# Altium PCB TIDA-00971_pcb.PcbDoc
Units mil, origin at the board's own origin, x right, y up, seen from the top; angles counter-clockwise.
Board outline 1950 x 2000 mil, 2 copper layers (Top Layer, Bottom Layer), stack 62 mil thick; 42 components, 22 nets, 111 pads, 73 vias.
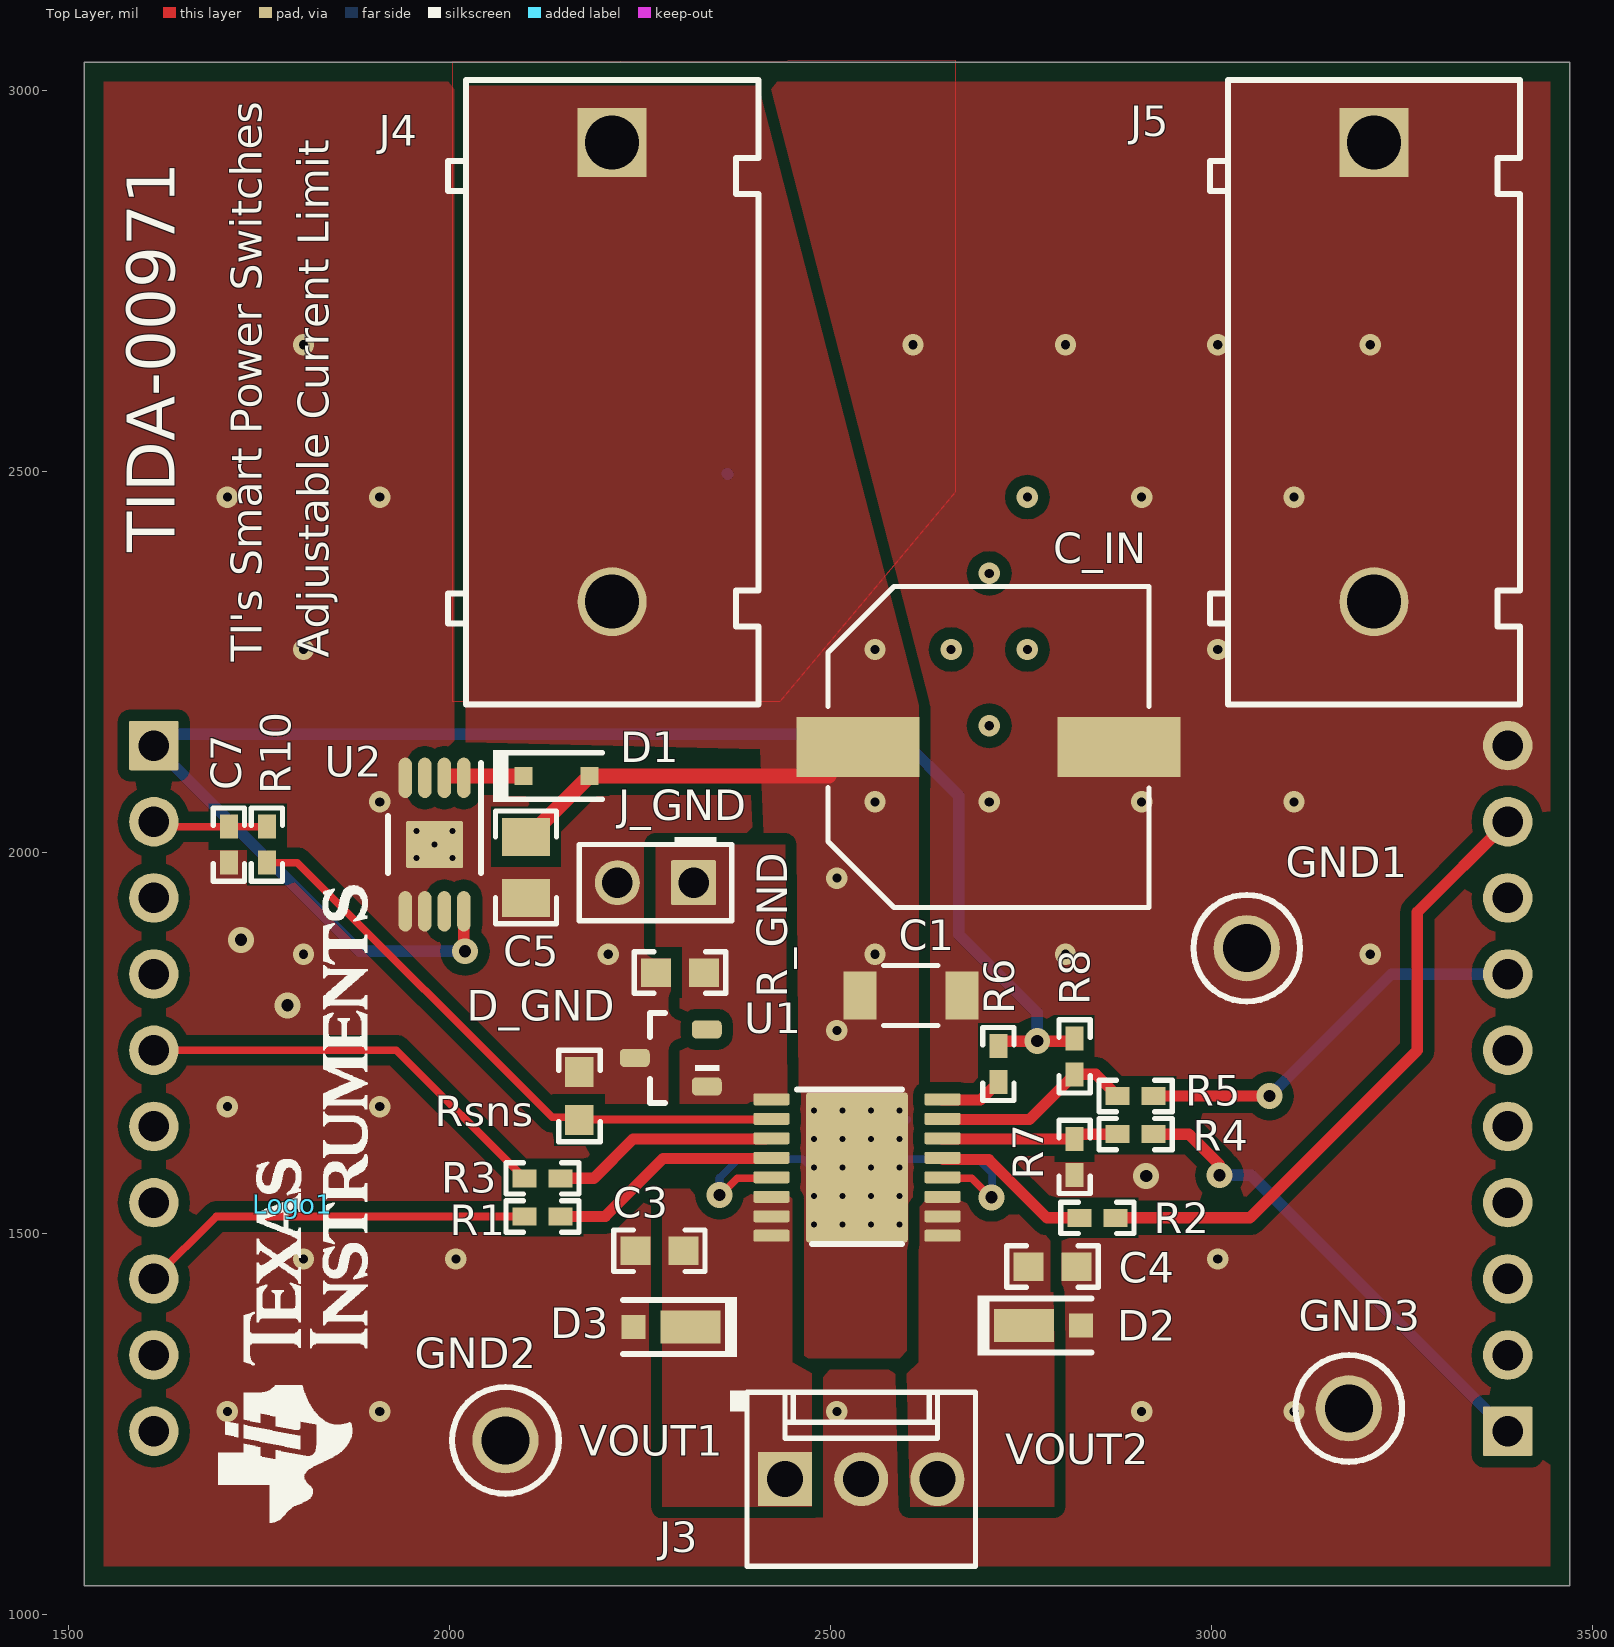
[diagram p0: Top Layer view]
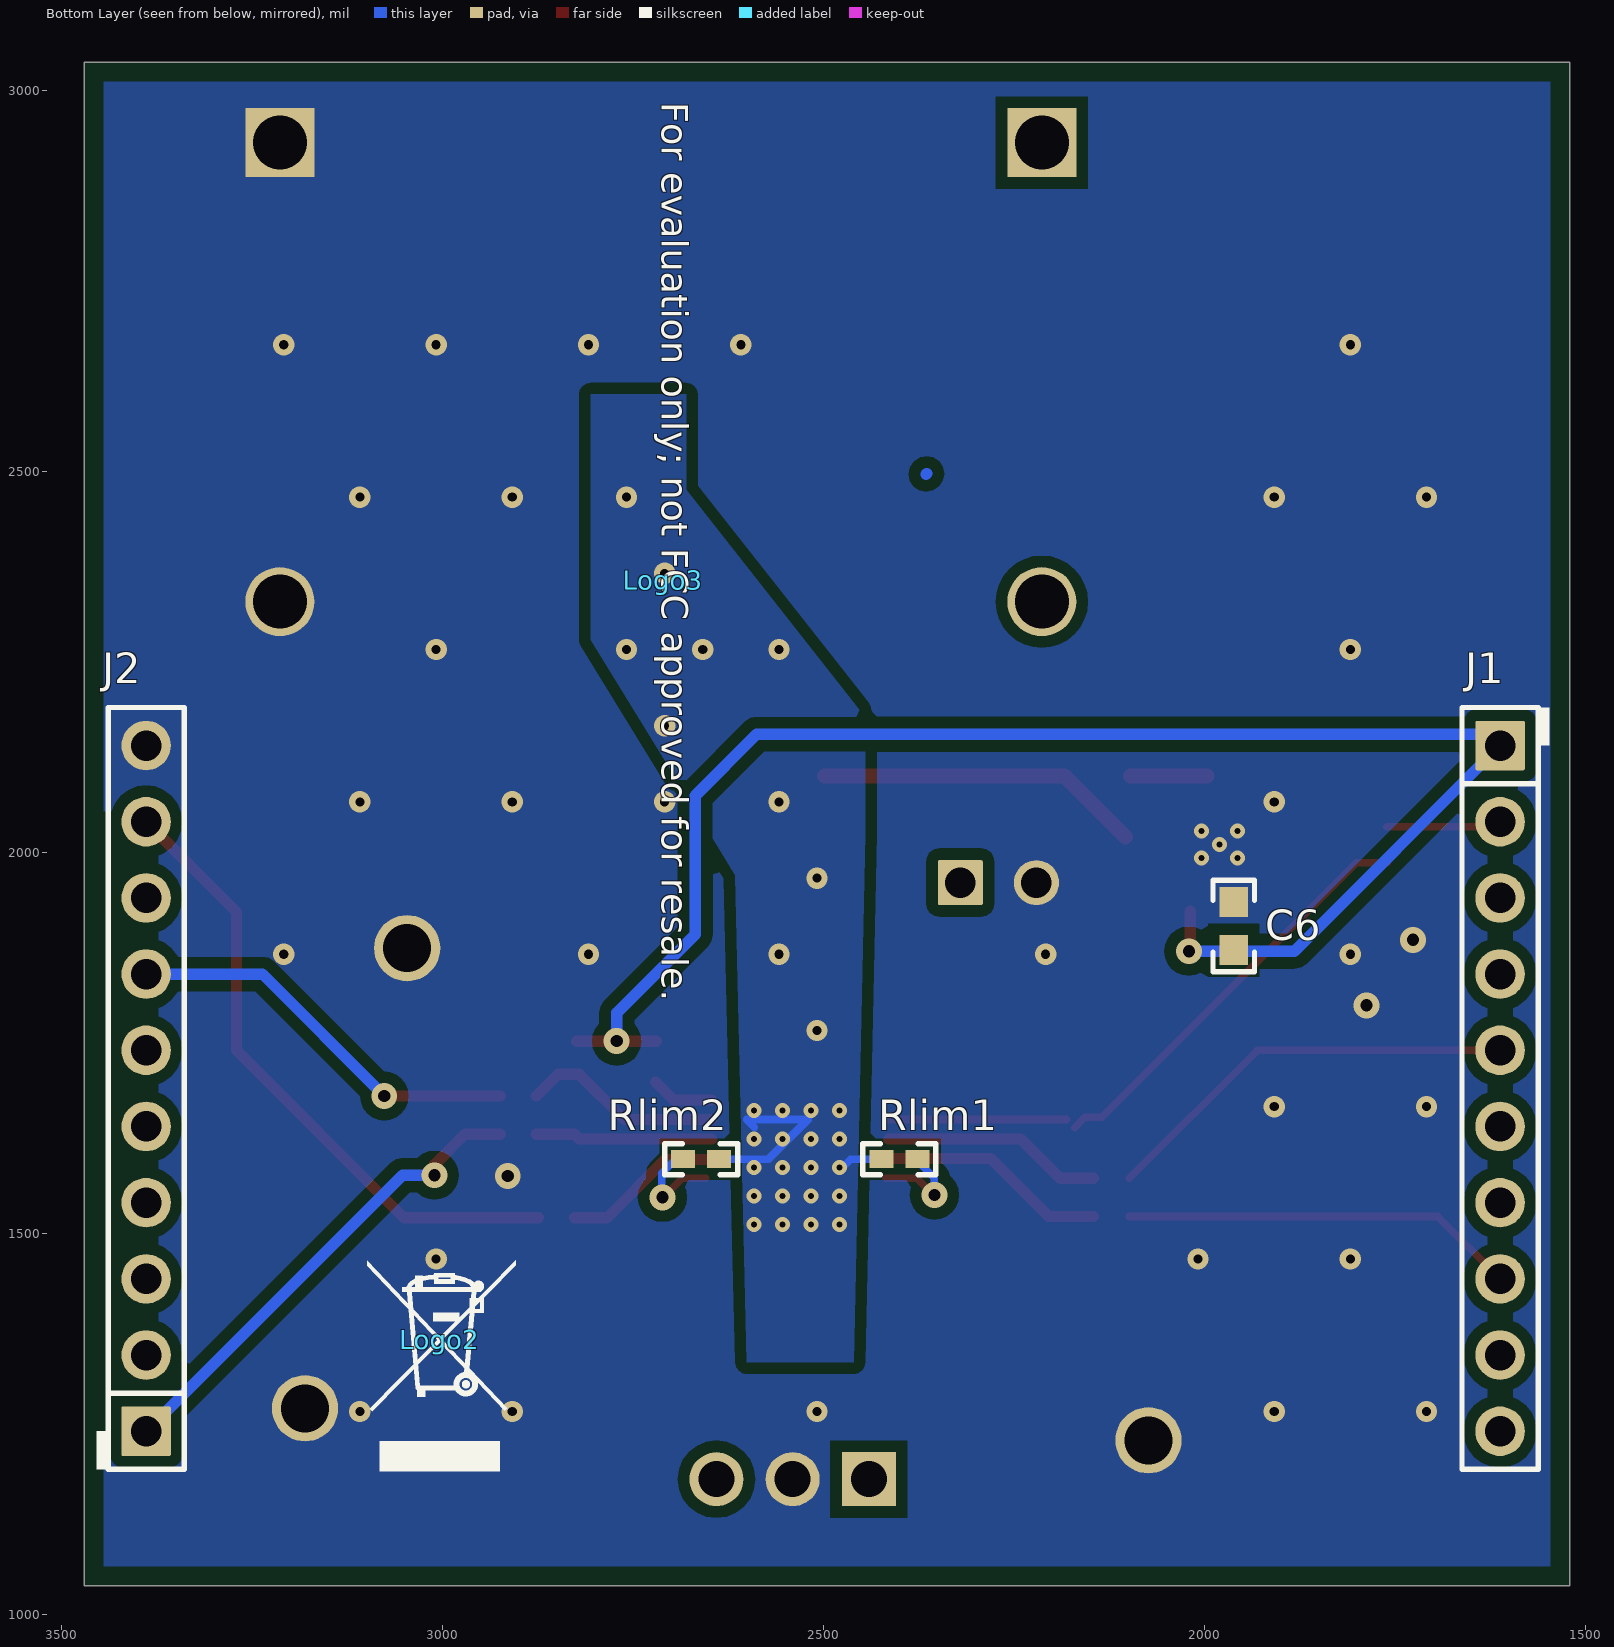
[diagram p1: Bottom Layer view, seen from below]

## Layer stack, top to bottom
Top Solder: solder mask 0.4, Solder Resist, Dk 3.5
Top Layer: signal copper 1.4
Dielectric1: core 59.2, FR-4, Dk 4.8
Bottom Layer: signal copper 1.4
Bottom Solder: solder mask 0.4, Solder Resist, Dk 3.5

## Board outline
1520,1037 3470,1037 3470,3037 1520,3037

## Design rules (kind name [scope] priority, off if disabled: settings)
AcuteAngle [All] p1: minimum=4.50000000000000E+0001 checktracksonly=FALSE
AssemblyTestPointUsage [All] p1: valid=2
BoardOutlineClearance BoardOutlineClearance_banana [(HasFootprint('571-0100') AND HasFootprint('571-0500'))] p1: gap=0 ignorepadtopadclearanceinfootprint=FALSE
BoardOutlineClearance BoardOutlineClearance_MountingHoles [OnCopper and InComponentClass('Mounting Holes')] p2: gap=40 ignorepadtopadclearanceinfootprint=FALSE
BoardOutlineClearance BoardOutlineClearance_Poly [OnCopper and IsPoly] p3: gap=25 ignorepadtopadclearanceinfootprint=FALSE
BoardOutlineClearance [OnCopper and Not InComponentClass('Logo') and not InComponentClass('FiducialMark') and not InRegion(1000,500,4000,800) and not InPoly] p4: gap=75 ignorepadtopadclearanceinfootprint=FALSE except(10: THPad-OutlineEdge THPad-CavityEdge THPad-CutoutEdge THPad-SplitBarrior THPad-SplitContinuation; 20: Track-OutlineEdge Track-CavityEdge Track-CutoutEdge Track-SplitBarrior Track-SplitContinuation)
Clearance Clearance_Keepouts [((IsTrack Or IsArc) And Not InPoly) And IsFree and IsKeepOut vs ((IsTrack Or IsArc) And Not InPoly) And IsFree and IsKeepOut] p1: gap=0 ignorepadtopadclearanceinfootprint=FALSE
Clearance Clearance_Poly [InPolygon] p2: gap=15 ignorepadtopadclearanceinfootprint=FALSE
Clearance Clearance_FiducialMark [IsKeepOut and InComponentClass('FiducialMark') vs IsPad and InComponentClass('FiducialMark')] p3: gap=0 ignorepadtopadclearanceinfootprint=FALSE
Clearance [All] p4: gap=7.87 ignorepadtopadclearanceinfootprint=FALSE except(0: Arc-Hole Track-Hole SMDPad-Hole THPad-Hole Via-Hole Fill-Hole Poly-Hole Region-Hole Text-Hole)
ComponentClearance ComponentClearance_Logo [(HasFootprint('FCC_disclaimer') AND HasFootprint('TI_Stacked_Overlay_Small') AND HasFootprint('WEEE_Minimum') AND HasFootprint('WorksWithTILaunchPad'))] p1: gap=0 collisioncheckmode=3 verticalgap=0 showdistances=FALSE
ComponentClearance ComponentClearance_MountingHoles_FiducialMarks [InComponentClass('Mounting Holes') vs InComponentClass('FiducialMark')] p2: gap=50 collisioncheckmode=3 verticalgap=10 showdistances=FALSE
ComponentClearance ComponentClearance_Shunt [InComponentClass('Header') vs InComponentClass('Shunt')] p3: gap=0 collisioncheckmode=3 verticalgap=0 showdistances=FALSE
ComponentClearance ComponentClearance_ScrewToNut [(HasFootprint('NY PMS 440 0025 PH')) vs (HasFootprint('Keystone_1902C'))] p4: gap=5 collisioncheckmode=3 verticalgap=10 showdistances=FALSE
ComponentClearance ComponentClearance_MountingHoles [InComponentClass('Mounting Holes')] p5: gap=250 collisioncheckmode=3 verticalgap=100000 showdistances=FALSE
ComponentClearance ComponentClearance_SmallPassives [HasFootprint('0201*') or HasFootprint('0402*') or HasFootprint('0508') or HasFootprint('0603*') or HasFootprint('0612') or HasFootprint('0805*') or HasFootprint('0815*') or HasFootprint('0830*') or HasFootprint('1206*') or HasFootprint('1210*') or HasFootprint('1808*') or HasFootprint('1812*') or HasFootprint('1825*') or HasFootprint('2010*') or HasFootprint('2220*') or HasFootprint('2225*') or HasFootprint('2512*') or HasFootprint('2728*') or HasFootprint('3518*') vs HasFootprint('0201*') or HasFootprint('0402*') or HasFootprint('0508') or HasFootprint('0603*') or HasFootprint('0612') or HasFootprint('0805*') or HasFootprint('0815*') or HasFootprint('0830*') or HasFootprint('1206*') or HasFootprint('1210*') or HasFootprint('1808*') or HasFootprint('1812*') or HasFootprint('1825*') or HasFootprint('2010*') or HasFootprint('2220*') or HasFootprint('2225*') or HasFootprint('2512*') or HasFootprint('2728*') or HasFootprint('3518*')] p6: gap=14.96 collisioncheckmode=3 verticalgap=10 showdistances=FALSE
ComponentClearance ComponentClearance_THtoSMT [IsThruComponent vs IsSMTComponent] p7: gap=40 collisioncheckmode=3 verticalgap=30 showdistances=FALSE
ComponentClearance ComponentClearance_THtoTH [IsThruComponent vs IsThruComponent] p8: gap=30 collisioncheckmode=3 verticalgap=30 showdistances=FALSE
ComponentClearance [All] p9: gap=30 collisioncheckmode=3 verticalgap=10 showdistances=FALSE
DiffPairsRouting [All] p1: maxlimit=100 minlimit=10 mostfreqgap=10 toplayer_minwidth=15 toplayer_maxwidth=15 toplayer_prefwidth=15 bottomlayer_minwidth=15 bottomlayer_maxwidth=15 bottomlayer_prefwidth=15 maxuncoupledlength=1000
FabricationTestPointUsage TestPointUsage [All] p1: valid=2 allowmultiple=FALSE
FabricationTestpoint Testpoint [All] p1: side=3 testpointundercomponent=TRUE minsize=40 maxsize=100 preferedsize=60 minholesize=0 maxholesize=40 preferedholesize=32 testpointgrid=1 allowsidetop=TRUE allowsidebottom=TRUE usegrid=TRUE gridtolerance=0.01
FanoutControl Fanout_LCC [IsLCC] p1: bgadir=Out bgaviamode=Centered fanoutstyle=Auto fanoutdirection=Alternating viagrid=1 // Fanout_LCC (Default Rule)
FanoutControl Fanout_BGA [IsBGA] p2: bgadir=Out bgaviamode=Centered fanoutstyle=Auto fanoutdirection=Alternating viagrid=1 // Fanout_BGA (Default Rule)
FanoutControl Fanout_Default [All] p4: bgadir=Out bgaviamode=Centered fanoutstyle=Auto fanoutdirection=Alternating viagrid=1 // Fanout_Default (Default Rule)
FanoutControl Fanout_Small [(CompPinCount < 5)] p5: bgadir=Out bgaviamode=Centered fanoutstyle=Auto fanoutdirection=OutThenIn viagrid=1 // Fanout_Small (Default Rule)
HoleSize [All] p1: absolutevalues=TRUE maxlimit=251 minlimit=7.87 maxpercent=80.000 minpercent=20.000
MinimumAnnularRing MinimumAnnularRing_ThermalPadVias [IsVia and InAnyComponent] p1: minimumring=5.91
MinimumAnnularRing [All] p2: minimumring=8
MinimumSolderMaskSliver MinimumSolderMaskSliver_Logo [InComponentClass('Logo') vs InComponentClass('Logo')] p1: minsoldermaskwidth=0.7
MinimumSolderMaskSliver [All] p2: minsoldermaskwidth=3.94
PlaneClearance [All] p1: clearance=15
PlaneConnect [All] p1: planeconnectstyle=Relief reliefexpansion=10 reliefentries=4 reliefconductorwidth=10 reliefairgap=10
PolygonConnect [All] p1: connectstyle=Direct reliefconductorwidth=10 reliefentries=4 polygonreliefangle="90 Angle" airgapwidth=10
RoutingVias ThermalPadVias [IsVia and InAnyComponent] p1: holewidth=7.87 width=19.68 viastyle="Through Hole" minholewidth=7.87 minwidth=19.68 maxholewidth=12.99 maxwidth=23.62
RoutingVias [All] p2: holewidth=16 width=34 viastyle="Through Hole" minholewidth=7.87 minwidth=26 maxholewidth=40 maxwidth=65
SilkToBoardRegionClearance [Not ((IsComment or IsDesignator) And (Hide <> 'False')) and not InRegion(1000,500,4000,800)] p1:
SilkToSilkClearance SilkToSilkClearance_Pb-FreeLogo [(HasFootprint('Pb-Free_Overlay_Medium') OR HasFootprint('Pb-Free_Overlay_Small')) vs (HasFootprint('Pb-Free_Overlay_Medium') OR HasFootprint('Pb-Free_Overlay_Small'))] p1: silktosilkclearance=0
SilkToSilkClearance [All] p2: silktosilkclearance=4
SilkToSolderMaskClearance SilkToComponentPadClearance [(IsPad or IsFill or IsRegion) and InAnycomponent] p1: minsilkscreentomaskgap=5 clearancetoexposedcopper=TRUE
SilkToSolderMaskClearance "Silk to Solder Mask Opening" [All] p2: minsilkscreentomaskgap=4 clearancetoexposedcopper=FALSE
SolderMaskExpansion [All] p1: expansion=1.97
Width [All] p1: maxlimit=100 minlimit=6 preferedwidth=10 checkconnectedcopper=TRUE
14 further rules are at their usual default settings.

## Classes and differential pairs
component class AssemblyNote: ZZ1 ZZ2 ZZ3 ZZ4
component class EVM_Hardware: Logo1 Logo2 Logo3 ZZ1 ZZ2 ZZ3 ZZ4
component class Logo: Logo1
component class TIDA-00971_main_schematic: C1 C3 C4 C5 C6 C7 C_IN D1 D2 D3 D_GND GND1 GND2 GND3 J1 J2 J3 J4 J5 J_GND R1 R2 R3 R4 R5 R6 R7 R8 R10 R_GND Rlim1 Rlim2 Rsns U1 U2
component class Header: J1 J2 J_GND

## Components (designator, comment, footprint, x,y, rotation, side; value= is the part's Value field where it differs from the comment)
C1 "C1206C225K5RACAUTO7210" 1206_180 2605,1812 r0 top value=2.2uF
C3 "C0603C223K3RACTU" 0603 2275,1477 r180 top value=0.022uF
C4 "C0603C223K3RACTU" 0603 2791,1456 r0 top value=0.022uF
C5 "08055C105K4Z2A" 0805_HV 2100,1980 r270 top value=1uF
C6 "GRT188C81C106ME13D" 0603 1961,1903 r90 bottom value=10uF
C7 "CGA2B2C0G1H101J050BA" 0402 1710,2010 r270 top value=100pF
C_IN "EEE-FK1H151P" SM_RADIAL_G 2707,2138 r0 top value=150uF
D1 "ZLLS400QTA" SOD-323 2140,2100 r0 top value=40V
D2 "MSE1PGHM3/89A" MicroSMP 2779,1379 r0 top value=400V
D3 "MSE1PGHM3/89A" MicroSMP 2290,1377 r180 top value=400V
D_GND "BAS21HMFHT116" SOT-23 2290,1730 r180 top value=200V
GND1 "5011" Keystone5011 3046,1874 r0 top
GND2 "5011" Keystone5011 2073,1228 r0 top
GND3 "5011" Keystone5011 3180,1270 r0 top
J1 "TSW-110-07-G-S" TSW-110-07-G-S 1611.5,1690 r270 bottom
J2 "TSW-110-07-G-S" TSW-110-07-G-S 3388.5,1690 r90 bottom locked
J3 "22-27-2031" MOLEX_22-27-2031 2540,1177 r0 top
J4 "571-0500" 571-0500 2213,2630 r270 top
J5 "571-0100" 571-0100 3213,2630 r270 top
J_GND "PEC02SAAN" CONN_PEC02SAAN 2270,1960 r180 top
Logo1 "Texas Instruments" TI_Stacked_Overlay_Small 1794,1538 r90 top
Logo2 "WEEE logo" WEEE_Minimum 3003,1360 r180 bottom
Logo3 "FCC disclaimer" FCC_disclaimer 2710,2357 r270 bottom
R1 "CRCW040215K0JNED" 0402 2121.65,1521.81 r0 top value=15k
R2 "CRCW040215K0JNED" 0402 2850,1520 r180 top value=15k
R3 "CRCW040215K0JNED" 0402 2121.65,1571.81 r0 top value=15k
R4 "CRCW040215K0JNED" 0402 2900,1630 r0 top value=15k
R5 "CRCW040215K0JNED" 0402 2900,1680 r0 top value=15k
R6 "CRCW040215K0JNED" 0402 2720,1722 r270 top value=15k
R7 "ERJ-2GE0R00X" 0402 2820,1600 r90 top value=0
R8 "ERJ-2GE0R00X" 0402 2820,1732 r270 top value=0
R10 "CRCW040210K0JNED" 0402 1760,2010 r270 top value=10k
R_GND "RC0603JR-074K7L" 0603 2301.98,1841.98 r0 top value=4.7k
Rlim1 "CRCW040220K0FKED" 0402 2400,1597 r180 bottom value=20.0k
Rlim2 "CRCW040224K9FKED" 0402 2660,1597 r0 bottom value=24.9k
Rsns "CRCW06033K01FKEA" 0603 2170,1680 r270 top value=3.01k
U1 "TPS2HB16BQPWPRQ1" TPS1HA08-Q1_L 2534.4,1586.15 r0 top
U2 "TPS7B8233QDGNRQ1" DGN0008D_N 1980,2010 r270 top
ZZ1 "This Assembly Note is for PCB labels only" AssemblyNoteLabel 185,3938 r0 top
ZZ2 "These assemblies are ESD sensitive, ESD precautions shall be observed." AssemblyNote 185,3829.11 r0 top
ZZ3 "These assemblies must be clean and free from flux and all contaminants. Use of no clean flux is not acceptable." AssemblyNote 185,3740.56 r0 top
ZZ4 "These assemblies must comply with workmanship standards IPC-A-610 Class 2, unless otherwise specified." AssemblyNote 185,3652 r0 top

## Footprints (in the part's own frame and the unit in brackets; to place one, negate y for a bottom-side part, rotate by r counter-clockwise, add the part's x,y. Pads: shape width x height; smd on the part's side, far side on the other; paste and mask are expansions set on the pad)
0402 [mm] "0402 from SM-752 data"
  rect 0.8x0.6 smd: 1(-0.6,0) 2(0.6,0)
  silkscreen extent -1.22,-0.52 1.22,0.52, body extent -0.55,-0.3 0.55,0.3, height 0.6
571-0100 [mm] "Deltron Emcon recommended land pattern 2003-10-13"
  rect 2.3x2.3 hole 1.8: 1(-7.65,0)
  round 2.3 hole 1.8: 2(7.65,0)
  silkscreen extent -9.74,-5.47 11.09,4.88, body extent -12.28,-5.48 11.09,4.88, height 12.41
571-0500 [mm] "Deltron Emcon recommended land pattern 2003-10-13"
  rect 2.3x2.3 hole 1.8: 1(-7.65,0)
  round 2.3 hole 1.8: 2(7.65,0)
  silkscreen extent -9.74,-5.47 11.09,4.88, body extent -12.28,-5.48 11.09,4.88, height 12.41
0603 [mm] "0603 from SM-752 data"
  rect 1x0.95 smd: 1(-0.8,0) 2(0.8,0)
  silkscreen extent -1.52,-0.69 1.52,0.69, body extent -0.87,-0.47 0.87,0.47, height 1
0805_HV [mil] "0805 with 30mil clearance between pads"
  rect 50x63 smd: 1(-40,0) 2(40,0)
  silkscreen extent -74,-40 74,40, body extent -43,-29 43,29, height 57
1206_180 [mm] "1206_180"
  rect 1.1x1.6 smd: 1(-1.7,0) 2(1.7,0)
  silkscreen extent -0.9,-1 0.9,1, body extent -1.75,-0.95 1.75,0.95, height 1.8
AssemblyNote [mil] "Assembly Note"
AssemblyNoteLabel [mil] "Assembly Note for PCB Labels"
CONN_PEC02SAAN [mm] "SULLINS"
  rrect7% 1.5x1.5 hole 1.016: 1(-1.27,0)
  round 1.5 hole 1.016: 2(1.27,0)
  silkscreen extent -2.54,-1.52 2.54,1.27, body extent -2.54,-1.27 2.54,1.27, height 8.38
DGN0008D_N [mm] "TSOP, 8-Leads, Body 3x3mm, Pitch 0.65mm, Thermal Pad 1.89x1.57mm, IPC Medium Density"
  rrect100% 1.35x0.45 smd: 1(-2.225,0.975) 2(-2.225,0.325) 3(-2.225,-0.325) 4(-2.225,-0.975) 5(2.225,-0.975) 6(2.225,-0.325) 7(2.225,0.325) 8(2.225,0.975)
  rrect6% 1.57x1.89 smd: 9(0,0)
  silkscreen extent -2.73,-1.55 0.95,1.55, body extent -2.46,-1.5 2.46,1.5, height 1.1
FCC_disclaimer [mil]
Keystone5011 [mil] "Keystone Multipurpose loops"
  round 87 hole 63: 1(0,0)
  silkscreen extent -70,-70 70,70, body extent -63,-63 63,62, height 319
MicroSMP [mm] "SMD, 2-Leads, Body 2.2x1.3mm"
  rect 2x1.1 smd: 1(-0.65,0)
  rect 0.8x0.8 smd: 2(1.25,0)
  silkscreen extent -2.2,-1 1.6,1, body extent -1.15,-0.7 1.15,0.7, height 0.75
MOLEX_22-27-2031 [mm] "MOLEX"
  rect 1.8x1.8 hole 1.2: 1(-2.54,0)
  round 1.8 hole 1.2: 2(0,0) 3(2.54,0)
  silkscreen extent -4.37,-2.9 3.81,2.96, body extent -3.81,-2.9 3.81,2.9, height 11.72
SM_RADIAL_G [mm] "10 x 10.2mm:  Panasonic G"
  rect 4.1x2 smd: 1(-4.35,0) 2(4.35,0)
  silkscreen extent -5.35,-5.35 5.35,5.35, body extent -5.25,-5.25 5.25,5.25, height 10.5
SOD-323 [mm] "NXP recommended land pattern"
  rect 0.6x0.6 smd paste-0.05: 1(-1.1,0) 2(1.1,0)
  silkscreen extent -2.11,-0.86 1.53,0.86, body extent -1.3,-0.67 1.3,0.68, height 1.1
SOT-23 [mm] "SOT23, 3-Leads, Body 2.9x1.3mm, Pitch 0.95mm, Lead Span 2.5mm, IPC Medium Density"
  rrect50% 1x0.6 smd: 1(-1.2,0.95) 2(-1.2,-0.95) 3(1.2,0)
  silkscreen extent -1.63,-1.5 0.7,1.5, body extent -1.16,-1.45 1.21,1.45, height 1
TI_Stacked_Overlay_Small [mil]
  silkscreen extent -418,-98 418,98
TPS1HA08-Q1_L [mm] "TSOP, 16-Leads, Body 5x4.4mm, Pitch 0.65mm, Thermal Pad 2.41x3.29 mm, IPC High Density"
  rrect25% 1.2x0.4 smd: 1(-2.85,2.275) 2(-2.85,1.625) 3(-2.85,0.975) 4(-2.85,0.325) 5(-2.85,-0.325) 6(-2.85,-0.975) 7(-2.85,-1.625) 8(-2.85,-2.275) 9(2.85,-2.275) 10(2.85,-1.625) 11(2.85,-0.975) 12(2.85,-0.325) 13(2.85,0.325) 14(2.85,0.975) 15(2.85,1.625) 16(2.85,2.275)
  rrect4% 2.5x2.78 on Top Solder: 17(0,-0.155)
  rrect4% 2.5x2.78 on Top Paste: 17(0,-0.155)
  rrect6% 3.4x5 smd paste-1.7 mask-1.7: 17(0,0)
  rrect27% 1.71x0.37 on Top Solder: 17(0,1.36)
  rrect27% 1.71x0.37 on Top Paste: 17(0,1.36)
  silkscreen extent -2,-2.55 1.5,2.6, body extent -3.21,-2.5 3.21,2.5, height 0.99
TSW-110-07-G-S [mm] "Samtec 100mil, 1x10, 230 mil above insulator"
  rrect6% 1.65x1.65 hole 1.016: 1(-11.43,0)
  round 1.65 hole 1.016: 2(-8.89,0) 3(-6.35,0) 4(-3.81,0) 5(-1.27,0) 6(1.27,0) 7(3.81,0) 8(6.35,0) 9(8.89,0) 10(11.43,0)
  silkscreen extent -12.7,-1.27 12.7,1.65, body extent -12.7,-1.27 12.7,1.27, height 8.38
WEEE_Minimum [mil] "WEEElie bin"
  silkscreen extent -95,-172 99,104

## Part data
C1: library part CMP-0080745-1, "CAP, CERM, 2.2 µF, 50 V,+/- 10%, X7R, AEC-Q200 Grade 1, 1206", Cap_Case=1206, Manufacturer=KEMET, Supplier Part Number 1=399-19155-1-ND, TempCo=X7R, Tolerance_%=10%, Value2=50V, ValueDisplayed=2.2µF
C3 C4: library part CMP-0006899-4, "CAP, CERM, 0.022 uF, 25 V, +/- 10%, X7R, 0603", Cap_Case=0603, Manufacturer=Kemet, Supplier Part Number 1=399-1094-1-ND, TempCo=X7R, Tolerance_%=10%, Value1=Unknown, Value2=25V, ValueDisplayed=0.022uF
C5: library part CMP-0083705-1, "CAP, CERM, 1 µF, 50 V,+/- 10%, X7R, AEC-Q200 Grade 1, 0805", Cap_Case=0805, Manufacturer=AVX, Supplier Part Number 1=478-9557-1-ND, TempCo=X7R, Tolerance_%=10%, Value2=50V, ValueDisplayed=1µF
C6: library part CMP-0085644-1, "CAP, CERM, 10 µF, 16 V,+/- 20%, X6S, AEC-Q200 Grade 2, 0603", Cap_Case=0603, Manufacturer=MuRata, TempCo=X6S, Tolerance_%=20%, Value2=16V, ValueDisplayed=10µF
C7: library part CMP-0006308-2, "CAP, CERM, 100 pF, 50 V, +/- 5%, C0G/NP0, AEC-Q200 Grade 1, 0402", Cap_Case=0402, Manufacturer=TDK, Supplier Part Number 1=445-5596-1-ND, TempCo=C0G/NP0, Tolerance_%=5%, Value1=Unknown, Value2=50V, ValueDisplayed=100pF
C_IN: library part CMP-0011178-2, "CAP, AL, 150 uF, 50 V, +/- 20%, 0.18 ohm, AEC-Q200 Grade 2, SMD", Cap_Case=G, Manufacturer=Panasonic, Supplier Part Number 1=PCE3810CT-ND, Tolerance_%=20%, Value1="0.18 ohm", Value2=50V, ValueDisplayed=150uF
D1: library part CMP-0028792-2, "Diode, Schottky, 40 V, 0.52 A, AEC-Q101, SOD-323", Manufacturer="Diodes Inc.", Value1=0.52A, Value2=V
D2 D3: library part CMP-0029173-2, "Diode, Standard Recovery Rectifier, 400 V, 1 A, AEC-Q101, MicroSMP", Manufacturer=Vishay-Semiconductor, Value1=1A, Value2=1.1V
D_GND: library part CMP-0080708-2, "Diode, Switching, 200 V, 0.2 A, AEC-Q101, SOT-23", Manufacturer=Rohm, Value1=0.2A, Value2=1.25V
GND1 GND2 GND3: library part CMP-0055148-1, "Test Point, Multipurpose, Black, TH", Color=Black, Manufacturer=Keystone, Supplier Part Number 1=36-5011-ND
J1 J2: library part CMP-0075422-1, "Header, 100mil, 10x1, Gold, TH", Color=Black, Current_A=6.3A, Manufacturer=Samtec, Supplier Part Number 1=SAM1029-10-ND, Voltage_V=550V
J3: library part CMP-0055191-1, "CONN HEADER 3POS .100 VERT TIN", Manufacturer=Molex, Supplier Part Number 1=WM4112-ND
J4: library part CMP-0055393-3, "Standard Banana Jack, insulated, 10A, red", Manufacturer="DEM Manufacturing", Supplier Part Number 1=30M0087
J5: library part CMP-0055389-3, "Standard Banana Jack, insulated, 10A, black", Manufacturer="DEM Manufacturing", Supplier Part Number 1=45M6896
J_GND: library part CMP-0002337-1, "Header, 100mil, 2x1, Tin, TH", Color=Black, Current_A=3A, Manufacturer="Sullins Connector Solutions", Supplier Part Number 1=S1012E-02-ND, Voltage_V=1.8kV
Logo1: library part CMP-0074838-1, "Texas Instrument Corporate Signature"
Logo2: library part CMP-0074769-1
Logo3: library part CMP-0074847-1, "FCC_disclaimer"
R1 R2 R3 R4 R5 R6: library part CMP-0026842-3, "RES, 15 k, 5%, 0.063 W, AEC-Q200 Grade 0, 0402", Manufacturer=Vishay-Dale, Power_W=63mW, Supplier Part Number 1=541-15KJCT-ND, TempCo="200 ppm/C", Tolerance_%=5%, Value2=0.063W, Value_Code=15k0, ValueDisplayed=15k
R7 R8: library part CMP-0026992-3, "RES, 0, 5%, 0.1 W, AEC-Q200 Grade 0, 0402", Manufacturer=Panasonic, Power_W=100mW, Supplier Part Number 1=P0.0JCT-ND, TempCo="600 ppm/C", Tolerance_%=5%, Value2=0.1W, Value_Code=0000, ValueDisplayed=0
R10: library part CMP-0026825-5, "RES, 10 k, 5%, 0.063 W, AEC-Q200 Grade 0, 0402", Manufacturer=Vishay-Dale, Power_W=63mW, Supplier Part Number 1=541-10KJCT-ND, TempCo="200 ppm/C", Tolerance_%=5%, Value2=0.063W, Value_Code=10k0, ValueDisplayed=10k
R_GND: library part CMP-0025927-5, "RES, 4.7 k, 5%, 0.1 W, 0603", Manufacturer=Yageo, Power_W=100mW, Supplier Part Number 1=311-4.7KGRCT-ND, TempCo="100 ppm/C", Tolerance_%=5%, Value2=0.1W, Value_Code=4k70, ValueDisplayed=4.7k
Rlim1: library part CMP-0026162-2, "RES, 20.0 k, 1%, 0.063 W, AEC-Q200 Grade 0, 0402", Manufacturer=Vishay-Dale, Power_W=63mW, Supplier Part Number 1=541-20.0KLCT-ND, TempCo="100 ppm/C", Tolerance_%=1%, Value2=0.063W, Value_Code=20k0, ValueDisplayed=20.0k
Rlim2: library part CMP-0026196-2, "RES, 24.9 k, 1%, 0.063 W, AEC-Q200 Grade 0, 0402", Manufacturer=Vishay-Dale, Power_W=63mW, Supplier Part Number 1=541-24.9KLCT-ND, TempCo="100 ppm/C", Tolerance_%=1%, Value2=0.063W, Value_Code=24k9, ValueDisplayed=24.9k
Rsns: library part CMP-0022371-4, "RES, 3.01 k, 1%, 0.1 W, AEC-Q200 Grade 0, 0603", Manufacturer=Vishay-Dale, Power_W=100mW, Supplier Part Number 1=541-3.01KHCT-ND, TempCo="100 ppm/C", Tolerance_%=1%, Value2=0.1W, Value_Code=3k01, ValueDisplayed=3.01k
U1: library part CMP-0076732-1, "40-V, 16-mOhm Dual-Channel Smart High-Side Switch, TPS1HA08-Q1 (TSSOP-16)", Alternate Manufacturer="Texas Instruments"
U2: library part CMP-0013312-4, "300mA High-Voltage Ultra-Low-Iq Low-Dropout (LDO) Regulator, DGN0008D (VSSOP-8)", Alternate Manufacturer="Texas Instruments"
ZZ1: library part CMP-0003616-3
ZZ2: library part CMP-0077236-1
ZZ3: library part CMP-0077237-1
ZZ4: library part CMP-0077238-1

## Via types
v1: diameter 28, hole 12, Top Layer to Bottom Layer, tented both sides, 39 vias
v2: diameter 19.68, hole 7.87, Top Layer to Bottom Layer, tented both sides, 14 vias
v3: diameter 19.68, hole 7.87, Top Layer to Bottom Layer, 11 vias
v4: diameter 34, hole 16, Top Layer to Bottom Layer, 9 vias

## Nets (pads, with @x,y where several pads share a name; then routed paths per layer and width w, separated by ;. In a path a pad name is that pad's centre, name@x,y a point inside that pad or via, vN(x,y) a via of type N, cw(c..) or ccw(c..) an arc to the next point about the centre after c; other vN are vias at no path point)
CLUTCH: C3.1 D3.1 J3.1 U1.6 U1.7 U1.8
COMPRESSOR: C4.1 D2.1 J3.3 U1.9 U1.10 U1.11
"Current Sense": C7.1 J1.2 R10.1 | length 142.1
  Top Layer w10: J1.2@1617.88,2033.62 C7.1 R10.1
EN1: J1.8 R1.1 | length 520.4
  Top Layer w10: J1.8 1693.31,1521.81 R1.1
EN2: J2.9 R2.1 | length 836.6
  Top Layer w15: R2.1 3050,1520 3270,1740 3270,1921.5 J2.9
GND: C1.2 C3.2 C4.2 C5.2 C6.2 C7.2 C_IN.2 D2.2 D3.2 D_GND.3 GND1.1 GND2.1 GND3.1 J2.10 J3.2 J5.1 J5.2 J_GND.2 R7.1 R_GND.1 Rsns.1 U2.4 U2.5 U2.6 U2.9
  other v1: 1708,1266 1908,1266 2508,1266 2908,1266 3108,1266 1808,1466 2008,1466 3008,1466 1708,1666 1908,1666 1808,1866 2208,1866 2808,1866 3208,1866 1908,2066 2708,2066 2908,2066 3108,2066 1808,2266 3008,2266 1708,2466 1908,2466 2908,2466 3108,2466 1808,2666 2608,2666 2808,2666 3008,2666 3208,2666
  other v3: 1956.38,1992.28 2003.62,1992.28 1980,2010 1956.38,2027.72 2003.62,2027.72
  other v4: 2914,1575 1787,1799 1726,1885
GND_IC: D_GND.1 J_GND.1 R_GND.2 U1.1
LATCH: J1.5 R3.1 | length 556.2
  Top Layer w10: J1.5 1929.84,1740 R3.1
NetD1_1: D1.1 U2.1 U2.2 | length 100.4
  Top Layer w20: U2.2@1996.34,2100 D1.1
NetJ2_1: J2.1 R4.2 | length 612.8
  Top Layer w15: R4.2 2970,1630 3010.18,1589.82 v4(3010.18,1576)
  Bottom Layer w15: v4(3010.18,1576) 3052,1576 J2.1@3373,1255
NetJ2_7: J2.7 R5.2 | length 531.2
  Top Layer w15: R5.2 v4(3076,1680)
  Bottom Layer w15: v4(3076,1680) 3236,1840 J2.7
NetR1_2: R1.2 U1.4 | length 300.1
  Top Layer w15: R1.2 2203.81,1521.81 2279.98,1597.98 U1.4@2413.86,1597.98
NetR2_2: R2.2 U1.13 | length 210.6
  Top Layer w15: U1.13@2647.5,1596.62 2707.17,1596.62 2783.78,1520 R2.2
NetR3_2: R3.2 U1.3 | length 290
  Top Layer w15: R3.2 2188.81,1571.81 2240.57,1623.57 U1.3@2413.86,1623.57
NetR6_2: R6.2 U1.16 | length 83.6
  Top Layer w15: U1.16@2646.14,1674.75 2696.37,1674.75 R6.2
NetR10_2: R10.2 Rsns.2 U1.2 | length 787.3
  Top Layer w10: R10.2 1800,1986.38 2134.43,1651.95 2156.56,1651.95 Rsns.2@2170,1638.5 ; Rsns.2@2180.65,1649.16 U1.2@2413.86,1649.16
NetRlim1_2: Rlim1.2 U1.5 | length 130.7
  Top Layer w10: v4@2354,1548 2354,1549 2377.2,1572.2 U1.5@2417.8,1572.2
  Bottom Layer w10: v4@2354,1548 v4(2354,1550) 2354,1572.62 Rlim1.2@2376.38,1595
NetRlim2_2: Rlim2.2 U1.12 | length 111.7
  Top Layer w10: U1.12@2654.2,1572.2 2684.8,1572.2 2702,1555 v4@2712,1555
  Bottom Layer w10: Rlim2.2@2695.62,1595 2712,1578.62 v4@2712,1555
  other v4: 2711,1547
SEL1: R4.1 R7.2 U1.14 | length 232.9
  Top Layer w15: U1.14@2646.14,1623.57 2819.94,1623.57 R7.2 2826.38,1630 R4.1
SEL2: R5.1 R8.2 U1.15 | length 266.5
  Top Layer w15: U1.15@2646.14,1649.16 2760.78,1649.16 R8.2 2848,1708.38 R5.1
V3V3: C6.1 J1.1 R6.1 R8.1 U2.8 | length 2139
  Top Layer w15: U2.8 2018.39,1871.61 v4(2020,1870) ; R6.1@2719,1752 v4(2771,1752) R8.1@2823.62,1752
  Bottom Layer w15: v4(2020,1870) 1881.5,1870 J1.1 1626.5,2155 2587,2155 2668,2074 2668,1892 2771,1789 v4(2771,1752)
VBB: C1.1 C5.1 C_IN.1 D1.2 J4.1 J4.2 Rlim1.1 Rlim2.1 U1.17@2534.4,1586.15 | length 714.9
  Top Layer w20: C5.1@2103.31,2020 D1.2 C_IN.1@2497.74,2100
  Bottom Layer w10: Rlim1.1 2463.9,1597 v2@2473.9,1587 ; 2590.5,1639.15 2600.5,1649.15 2519.85,1649.15 2572,1597 Rlim2.1
  other v1: 2508,1766 2558,1866 2508,1966 2558,2066 2708,2166 2558,2266 2658,2266 2758,2266 2708,2366 2758,2466
  other v2: 2478.3,1511.34 2515.7,1511.34 2553.1,1511.34 2590.5,1511.34 2478.3,1548.75 2590.5,1548.75 2478.3,1586.15 2590.5,1586.15 2478.3,1623.55 2590.5,1623.55 2478.3,1660.95 2515.7,1660.95 2553.1,1660.95 2590.5,1660.95
  other v3: 2515.7,1548.75 2553.1,1548.75 2515.7,1586.15 2553.1,1586.15 2515.7,1623.55 2553.1,1623.55
pads on no net: D_GND.2 J1.3 J1.4 J1.6 J1.7 J1.9 J1.10 J2.2 J2.3 J2.4 J2.5 J2.6 J2.8 U1.17@2534.4,1580.04 U1.17@2534.4,1639.69 U2.3 U2.7
copper on no net: | length 1.4
  Bottom Layer w15: 2364,2497 2365,2496

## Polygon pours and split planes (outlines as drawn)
no net on Top Layer "TOP_LAYER_NONET_P002" (solid, remove dead copper, pour order 2): 2003,3037 2003,2198 2434,2198 2664,2473.19 2664,3039
CLUTCH on Top Layer "TOP_LAYER_CLUTCH_P006" (solid, remove dead copper, pour order 6): 2279,1558 2449.71,1558 2449.71,1330.3 2475,1316 2475,1140.84 2279,1140.84
COMPRESSOR on Top Layer "TOP_LAYER_COMPRESSOR_P008" (solid, remove dead copper, pour order 8): 2790,1554 2615.29,1554 2615.29,1330.49 2600,1315.19 2604.03,1141.03 2793,1141.03 2793,1355
VBB on Top Layer "TOP_LAYER_VBB_P012" (solid, remove dead copper, pour order 12): 2021.07,2144.47 2021.07,3006 2404.93,3006 2615.29,2193 2615.29,2084 2615.29,1336 2444.71,1336 2407.21,2135.42
GND_IC on Top Layer "TOP_LAYER_GND_IC_P010" (solid, remove dead copper, pour order 10): 2443.39,1620 2300,1620 2301.98,1621.98 2301.98,1870.52 2269.26,1870.52 2270,1871.27 2270,2010 2440,2010
GND on Top Layer "TOP_LAYER_GND_P016" (solid, pour order 16): 1520,3037 3470,3037 3470,1037 1520,1037
VBB on Bottom Layer "BOTTOM_LAYER_VBB_P014" (solid, pour order 14): 2679.72,2475.72 2679.72,2601 2805,2601 2805,2279 2615.29,1970 2600,1330.49 2460,1330.49 2444.71,2024.37 2444.71,2177.14
GND on Bottom Layer "BOTTOM_LAYER_GND_P018" (solid, pour order 18): 1520,1037 3470,1037 3470,3037 1520,3037

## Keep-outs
Keep-Out Layer:
  text ".Layer_Name" at 577,-858.49 h60

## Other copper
Top Layer:
  text ".Layer_Name" at 577,-858.49 h60
Bottom Layer:
  text ".Layer_Name" at 577,-858.49 h60

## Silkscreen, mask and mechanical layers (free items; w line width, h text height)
Top Overlay:
  text "TIDA-00971" at 1660,2394 h108.27 r90
  text "Adjustable Current Limit" at 1855,2255 h70 r90
  text "TI's Smart Power Switches" at 1767,2250 h70 r90
  text "VOUT1" at 2170,1208 h40
  text "VOUT2" at 2729,1197 h40
  text ".Layer_Name" at 577,-858.49 h60
Bottom Overlay:
  text ".Layer_Name" at 577,-858.49 h60
Top Paste:
  text ".Layer_Name" at 577,-858.49 h60
Bottom Paste:
  text ".Layer_Name" at 577,-858.49 h60
Top Solder:
  text ".Layer_Name" at 577,-858.49 h60
  text ".Layer_Name" at 577,-858.49 h60
Bottom Solder:
  text ".Layer_Name" at 577,-858.49 h60
Drill Guide:
  text ".Layer_Name" at 577,-858.49 h60
M1 Board Outline:
  the board outline again, w10
  text ".Layer_Name" at 577,-858.49 h60
M2 Board Dimensions:
  rectangle: 125,-400 500,-275
  rectangle: 0,-275 125,-150
  lines w7: 0,-275 1000,-275 ; 125,-400 125,-150 ; 250,-400 250,-150 ; 500,-400 500,-150 ; 750,-400 750,-150 ; 0,-400 0,-150 1000,-150 1000,-400 0,-400
  text ".Layer_Name" at 577,-858.49 h60
M3 3D STEP Top:
  text ".Layer_Name" at 577,-858.49 h60
M4 3D STEP Bottom:
  text ".Layer_Name" at 577,-858.49 h60
M5 Assembly Top:
  lines w10: -292,-930.17 6308,-930.17 ; -292,-726.83 6310,-726.83 ; -292,-523.5 -292,-1133.5 3713,-1133.5 6310,-1133.5 6310,-523.5 -291.5,-523.5 -291.5,-1133.5 1284,-1133.5 ; 2173,-1133.5 2173,-523.5 ; 3440,-726.83 3440,-523.5 ; 4280,-726.83 4280,-523.5 ; 4902,-1140 4902,-937.17
  text "COMPONENTS MARKED 'DNP' SHOULD NOT BE POPULATED." at 1153.5,-318.5 h60
  text "ASSEMBLY VARIANT:" at 1153,-434 h60
  text ".VariantName" at 2189,-434 h60
  text "PCB VIEWED FROM TOP SIDE" at -228.5,-655.67 h60
  text "BOARD #:" at 2248,-655.67 h60
  text ".PRJ_Number" at 2793.5,-655.67 h60
  text "REV:" at 3638,-655.67 h60
  text ".PCB_Rev" at 3929.5,-655.67 h60
  text "SVN REV:" at 4476,-655.67 h60
  text ".VersionControl_RevNumber" at 4982,-655.67 h60
  text "TID #:" at 2248,-859 h60
  text ".TID" at 2793.5,-859 h60
  text "PLOT NAME =" at -228.5,-1064.34 h60
  text ".plot_File_Name" at 577,-1064.34 h60
  text "GENERATED    :" at 2250,-1064.34 h60
  text ".Print_Date" at 3119.5,-1064.34 h60
  text ".Print_Time" at 3848.5,-1064.34 h60
  text "TEXAS INSTRUMENTS" at 5113,-1064.34 h60
M6 Assembly Bottom:
  lines w10: -292.5,-727.33 6309.5,-727.33 ; -290.5,-930.67 6309.5,-930.67 ; 1115.5,-1140.5 1115.5,-937.67 ; 1737.5,-727.33 1737.5,-524 ; 2577.5,-727.33 2577.5,-524 ; 3844.5,-1134 3844.5,-524 ; 4733.5,-1134 6309,-1134 6309,-524 -292.5,-524 -292.5,-1134 2304.5,-1134 6309.5,-1134 6309.5,-524
  text "COMPONENTS MARKED 'DNP' SHOULD NOT BE POPULATED." at 6102,-318 h60
  text ".VariantName" at 5058,-434 h60
  text "ASSEMBLY VARIANT:" at 6097,-434 h60
  text ".VersionControl_RevNumber" at 1035.5,-656.17 h60
  text "SVN REV:" at 1541.5,-656.17 h60
  text ".PCB_Rev" at 2088,-656.17 h60
  text "REV:" at 2379.5,-656.17 h60
  text ".PRJ_Number" at 3224,-656.17 h60
  text "BOARD #:" at 3769.5,-656.17 h60
  text "PCB VIEWED FROM BOTTOM SIDE" at 6246,-656.17 h60
  text ".TID" at 3224,-859.5 h60
  text "TID #:" at 3769.5,-859.5 h60
  text "TEXAS INSTRUMENTS" at 904.5,-1064.84 h60
  text ".Print_Time" at 2169,-1064.84 h60
  text ".Print_Date" at 2898,-1064.84 h60
  text "GENERATED    :" at 3767.5,-1064.84 h60
  text ".plot_File_Name" at 5440.5,-1064.84 h60
  text "PLOT NAME =" at 6246,-1064.84 h60
M9 Title Sheet:
  drawing of 57 lines, arcs and shapes, not listed
  text "1" at 739.84,8036.5 h70
  text "2" at 3235.5,8036.5 h70
  text "3" at 5724.84,8036.5 h70
  text "4" at 8231.51,8036.5 h70
  text "5" at 10730.5,8036.5 h70
  text "6" at 13235.5,8036.5 h70
  text "A" at -416.5,6893.5 h70
  text "A" at 14383.5,6893.5 h70
  text "B" at -416.5,4513.5 h70
  text "B" at 14383.5,4513.5 h70
  text "C" at -416.5,2138.5 h70
  text "C" at 14383.5,2138.5 h70
  text "PROJECT TITLE:" at 11343.5,277.5 h45
  text ".PRJ_Title" at 11393.5,144.17 h70
  text "DESIGNED FOR:" at 11343.5,-23.5 h45
  text ".PRJ_Customer" at 11393.5,-163.5 h70
  text "D" at -416.5,-231.5 h70
  text "D" at 14383.5,-231.5 h70
  text "FILE NAME:" at 11343.5,-323.5 h45
  text ".PCB_File_Name_No_Path" at 11393.5,-443.5 h70
  text "Texas Instruments (TI) and/or its licensors do not warrant the accuracy or completeness of this specification" at 6374,-605.34 h45
  text "ENGINEER:" at 11343.5,-613.5 h45
  text "LAYOUT BY:" at 12848.5,-613.5 h45
  text "or any information contained therein. TI and/or its licensors do not warrant that this design will meet" at 6329.01,-718 h45
  text ".PRJ_Engineer" at 11393.5,-768.49 h70
  text ".PCB_Layout" at 12899,-768.49 h70
  text "the specifications, will be suitable for your application or fit for any particular purpose, or will operate in" at 6329.01,-830.67 h45
  text ".Layer_Name" at 577,-858.49 h60
  text "ALTIUM DESIGNER VERSION:" at 12848.5,-923.5 h45
  text "an implementation. TI and/or its licensors do not warrant that the design is production worthy. You should" at 6329.01,-943.33 h45
  text "completely validate and test your design implementation to confirm the system functionality for your application." at 6374,-1056 h45
  text ".print_Scale" at 11393.5,-1056.83 h70
  text ".Application_BuildNumber" at 12899,-1056.83 h70
  text "1" at 739.84,-1263.5 h70
  text "2" at 3235.5,-1263.5 h70
  text "3" at 5724.84,-1263.5 h70
  text "4" at 8231.51,-1263.5 h70
  text "5" at 10730.5,-1263.5 h70
  text "6" at 13235.5,-1263.5 h70
M10 Fab Notes:
  drawing of 189 lines, arcs and shapes, not listed
  text "DESIGN INFORMATION" at 12382.02,6356.17 h60
  text "MIN. TRACK WIDTH:" at 11737.46,6224.05 h60
  text "8" at 12833.7,6224.05 h60
  text "MIL" at 12988.46,6224.05 h60
  text "MIN. CLEARANCE:" at 11737.46,6099.92 h60
  text "0.2" at 12773.7,6099.93 h60
  text "mm" at 12988.46,6099.92 h60
  text "MIN. VIA PAD SIZE:" at 11737.46,5975.8 h60
  text "24" at 12803.71,5975.8 h60
  text "MIL" at 12988.46,5975.8 h60
  text "0.05mm (2MIL)" at 12432.46,5845.9 h60
  text "MINIMUM ANNULAR RING" at 11408.23,5837.67 h60
  text "EXTERNAL" at 13140.46,5837.67 h60
  text "PER" at 11608.23,5727.55 h60
  text "IPC-D-275 CLASS 2 LEVEL C" at 11828.23,5727.54 h60
  text "MIL, HOLES" at 13316.46,5627.07 h60
  text "+/-" at 12924,5618.48 h60
  text "+/-" at 13778,5618.48 h60
  text "REGISTRATION TOLERANCES:" at 11408.23,5617.42 h60
  text "METAL" at 12608,5617.42 h60
  text "5" at 13184.2,5617.42 h60
  text "3" at 14017.2,5617.42 h60
  text "MIL" at 14133.46,5617.42 h60
  text "HOLE SIZE TOLERANCE (UNLESS OTHERWISE SPECIFIED):" at 11408.23,5519.1 h60
  text "+/-" at 13778,5516.23 h60
  text "3" at 14017.2,5515.17 h60
  text "MIL" at 14133.46,5515.17 h60
  text "MATERIAL:" at 11333.46,5377.52 h60
  text "FR-4 High Tg" at 12319.9,5249 h60
  text "X" at 12175.46,5241.01 h60
  text "FR-408" at 11754.46,5236.49 h60
  text "OTHER" at 13242.46,5236.49 h60
  text "62 MIL (1.6mm) +/-10%" at 12074.56,5093.46 h60
  text "X" at 11954.46,5091.01 h60
  text "THICKNESS:" at 11408.23,5085.24 h60
  text "OTHER" at 13359.46,5085.24 h60
  text "TOLERANCE:" at 11408.23,4946.92 h60
  text "X" at 12256.46,4946.92 h60
  text "ANSI IPC-6012 TYPE 3 CLASS 2" at 12434.48,4946.92 h60
  text "OTHER +/-" at 12434.46,4802.73 h60
  text "BOW & TWIST:" at 11408.23,4657.54 h60
  text "X" at 12256.46,4657.54 h60
  text "ANSI IPC-6012 TYPE 3 CLASS 2" at 12434.48,4657.54 h60
  text "OTHER +/-" at 12434.46,4510.85 h60
  text "DRILLING:" at 11333.46,4380.23 h60
  text "NC_DRILL FILES" at 13094.46,4275.04 h60
  text "REFERENCE:" at 11408.23,4271.1 h60
  text "X" at 12065.46,4271.01 h60
  text "AS SHOWN" at 12243.46,4271.1 h60
  text "X" at 12966.46,4271.1 h60
  text "OTHER" at 13392.46,4128.85 h60
  text "PTH COPPER THICKNESS:" at 11407.91,4125.32 h60
  text "X" at 12547.14,4125.32 h60
  text "20-30 um" at 12675.14,4125.32 h60
  text "BOARD FINISH:" at 11333.46,3977.73 h60
  text "SILKSCREEN:" at 11488.68,3867.6 h60
  text "X" at 12446.46,3867.6 h60
  text "TOP" at 12563.46,3867.6 h60
  text "X" at 12956.46,3867.6 h60
  text "BOTTOM" at 13074.46,3867.6 h60
  text "SILKSCREEN COLOR:" at 11488.68,3712.41 h60
  text "X" at 12445.46,3712.41 h60
  text "WHITE" at 12563.46,3712.41 h60
  text "OTHER" at 13074.46,3712.41 h60
  text "X" at 12576.46,3568.96 h60
  text "GREEN" at 12694.46,3568.96 h60
  text "OTHER" at 13312.46,3568.96 h60
  text "SOLDER RESIST COLOR:" at 11488.68,3562.1 h60
  text "X" at 12576.46,3414.71 h60
  text "MATTE" at 12694.46,3414.71 h60
  text "SEMI-GLOSS" at 13312,3414.07 h60
  text "IMMERSION GOLD (ENIG)" at 12394.46,3241.94 h60
  text "ENEPIG" at 13732,3234.72 h60
  text "SURFACE FINISH:" at 11333.46,3233.72 h60
  text "X" at 12216.46,3233.72 h60
  text "IMM. TIN/SILVER OR EQUIV" at 11663,3096.4 h60
  text "OTHER" at 13094.46,3092.47 h60
  text "ARRAY/PANEL:" at 11333.46,2937.09 h60
  text "CUT AND TRIM PER M1 BOARD OUTLINE" at 12394.46,2928.87 h60
  text "N.C. ROUTE" at 12394.46,2792.9 h60
  text "X" at 13082.46,2792.9 h60
  text "V. SCORE" at 13260.46,2792.9 h60
  text "CERTIFICATION:" at 11333.46,2663.77 h60
  text "MATERIALS AND WORKMANSHIP FOR ALL PCBS" at 12058.46,2663.77 h60
  text "TO MEET OR EXCEED THE REQUIREMENTS OF:" at 12058.46,2569.71 h60
  text "X" at 11695.97,2441.08 h60
  text "ANSI IPC-A-600F CLASS ->" at 11823.96,2441.08 h60
  text "X" at 13471.97,2441.08 h60
  text "2" at 13581.96,2441.08 h60
  text "1" at 13266.96,2439.58 h60
  text "3" at 13935.96,2439.58 h60
  text "X" at 12507.97,2293.39 h60
  text "RoHS" at 12635.96,2293.39 h60
  text "OTHER" at 13280.36,2293.39 h60
  text "PER ORDER" at 13677.42,2293.39 h60
  text "ALL BOARDS MUST MEET OR EXCEED UL94-V0 REQUIREMENTS." at 11361,2139.57 h60
  text "PCB MUST BEAR THE UL94V-0 UL REGISTERED MATERIAL ID NUMBER" at 11361,2023.5 h60
  text "ADDITIONAL REQUIREMENTS:" at 11333.46,1854.08 h60
  text "MICROSECTION:" at 11408.23,1746.95 h60
  text "YES" at 12313.96,1746.95 h60
  text "REQUIRED" at 13175.46,1602.62 h60
  text "BARE BOARD ELEC. TEST:" at 11408.23,1599.76 h60
  text "NONE" at 12713.96,1599.76 h60
  text "X" at 13057.46,1599.76 h60
  text "PER ORDER" at 13767.46,1599.76 h60
  text "XX MIL VIAS REQUIRE NON-CONDUCTIVE FILL AND PLANARIZE" at 11576.38,1394.82 h59
  text "XX MIL VIAS REQUIRE CONDUCTIVE FILL AND PLANARIZE" at 11584.38,1290.84 h60
  text "OUTER XX MIL TRACES REQUIRE 50 OHM SINGLE-ENDED IMPEDANCE" at 11583.39,1127.46 h58
  text "LAYER 2 & 3 (INNER LAYERS) XX MIL WIDE, XX MIL SPACE / TRACES REQUIRE 100 OHM DIFFERENTIAL IMPEDANCE" at 11575.39,891.74 h60
  text ".Layer_Name" at 577,-858.49 h60
M11 Gerber Information:
  lines w10: -292,-930.17 6308,-930.17 ; -292,-726.83 6310,-726.83 ; -292,-523.5 -292,-1133.5 3713,-1133.5 6310,-1133.5 6310,-523.5 -291.5,-523.5 -291.5,-1133.5 1284,-1133.5 ; 2173,-1133.5 2173,-523.5 ; 3440,-726.83 3440,-523.5 ; 4280,-726.83 4280,-523.5 ; 4902,-1140 4902,-937.17
  text "ALL ARTWORK VIEWED FROM TOP SIDE" at -228.5,-655.67 h60
  text "BOARD #:" at 2248,-655.67 h60
  text ".PRJ_Number" at 2793.5,-655.67 h60
  text "REV:" at 3638,-655.67 h60
  text ".PCB_Rev" at 3929.5,-655.67 h60
  text "SVN REV:" at 4476,-655.67 h60
  text ".VersionControl_RevNumber" at 4982,-655.67 h60
  text "LAYER NAME =" at -228.5,-858.49 h60
  text "TID #:" at 2248,-859 h60
  text ".TID" at 2793.5,-859 h60
  text "PLOT NAME =" at -228.5,-1064.34 h60
  text ".plot_File_Name" at 577,-1064.34 h60
  text "GENERATED    :" at 2250,-1064.34 h60
  text ".Print_Date" at 3119.5,-1064.34 h60
  text ".Print_Time" at 3848.5,-1064.34 h60
  text "TEXAS INSTRUMENTS" at 5113,-1064.34 h60
M12 Stackup:
  drawing of 191 lines, arcs and shapes, not listed
  text "Layer" at 9797.84,7830 h60
  text "Name" at 10207.76,7830 h60
  text "Material" at 11137.5,7830 h60
  text "Thickness" at 11997.27,7830 h60
  text "Constant" at 12647.1,7830 h60
  text "Board Layer Stack" at 13216.96,7830 h60
  text "1" at 9797.84,7710 h60
  text "Top Overlay" at 10207.76,7710 h60
  text "2" at 9797.84,7590 h60
  text "Top Solder" at 10207.76,7590 h60
  text "Solder Resist" at 11137.5,7590 h60
  text "0.40mil" at 11997.27,7590 h60
  text "3.5" at 12647.1,7590 h60
  text "3" at 9797.84,7470 h60
  text "Top Layer" at 10207.76,7470 h60
  text "Copper" at 11137.5,7470 h60
  text "1.40mil" at 11997.27,7470 h60
  text "4" at 9797.84,7350 h60
  text "Dielectric1" at 10207.76,7350 h60
  text "FR-4" at 11137.5,7350 h60
  text "59.20mil" at 11997.27,7350 h60
  text "4.8" at 12647.1,7350 h60
  text "5" at 9797.84,7230 h60
  text "Bottom Layer" at 10207.76,7230 h60
  text "Copper" at 11137.5,7230 h60
  text "1.40mil" at 11997.27,7230 h60
  text "6" at 9797.84,7110 h60
  text "Bottom Solder" at 10207.76,7110 h60
  text "Solder Resist" at 11137.5,7110 h60
  text "0.40mil" at 11997.27,7110 h60
  text "3.5" at 12647.1,7110 h60
  text "7" at 9797.84,6990 h60
  text "Bottom Overlay" at 10207.76,6990 h60
  text ".Layer_Name" at 577,-858.49 h60
M13 Component Bodies Top:
  text ".Layer_Name" at 577,-858.49 h60
M14 Component Bodies Bottom:
  text ".Layer_Name" at 577,-858.49 h60
M15 Courtyards Top:
  text ".Layer_Name" at 577,-858.49 h60
M16 Courtyards Bottom:
  text ".Layer_Name" at 577,-858.49 h60
Drill Drawing:
  circle w10: c5348.9,2804.67 r22.14
  lines w10: 5326.76,2693.98 5337.83,2693.98 5337.83,2682.91 5359.97,2682.91 5359.97,2693.98 5371.04,2693.98 5371.04,2716.11 5359.97,2716.11 5359.97,2727.18 5337.83,2727.18 5337.83,2716.11 5326.76,2716.11 5326.76,2693.98 ; 5326.76,2893.22 5337.83,2893.22 5348.9,2882.15 5359.97,2893.22 5371.04,2893.22 5359.97,2904.29 5371.04,2915.36 5359.97,2915.36 5348.9,2926.43 5337.83,2915.36 5326.76,2915.36 5337.83,2904.29 5326.76,2893.22 ; 5326.76,2981.77 5371.04,2981.77 5371.04,3026.05 5326.76,3026.05 5326.76,2981.77 ; 5326.76,3081.4 5348.9,3092.47 5371.04,3081.4 5359.97,3103.54 5371.04,3125.67 5348.9,3114.6 5326.76,3125.67 5337.83,3103.54 5326.76,3081.4 ; 5326.76,3181.02 5326.76,3192.09 5337.83,3203.16 5326.76,3214.23 5326.76,3225.3 5337.83,3225.3 5348.9,3214.23 5359.97,3225.3 5371.04,3225.3 5371.04,3214.23 5359.97,3203.16 5371.04,3192.09 5371.04,3181.02 5359.97,3181.02 5348.9,3192.09 5337.83,3181.02 5326.76,3181.02 ; 5326.76,3324.92 5371.04,3324.92 5348.9,3280.64 5326.76,3324.92
  lines w12: 5286,2653.02 8398.94,2653.02 ; 5286,3350.38 8398.94,3350.38 ; 5601.63,2553.4 5601.63,3450 ; 5918.82,2553.4 5918.82,3450 ; 6540.56,2553.4 6540.56,3450 ; 6784.88,2553.4 6784.88,3450 ; 7145.22,2553.4 7145.22,3450 ; 7854.73,2553.4 7854.73,3450 ; 5286,2553.4 8398.94,2553.4 8398.94,3450 5286,3450 5286,2553.4
  text "Symbol" at 5345.77,3380.26 h72
  text "Quantity" at 5631.52,3380.26 h72
  text "Finished Hole Size" at 5948.7,3380.26 h72
  text "Plated" at 6570.45,3380.26 h72
  text "Hole Type" at 6814.77,3380.26 h72
  text "Drill Layer Pair" at 7175.11,3380.26 h72
  text "Hole Tolerance" at 7884.62,3380.26 h72
  text "25" at 5631.52,3280.64 h60
  text "7.87mil (0.200mm)" at 5948.7,3280.64 h60
  text "PTH" at 6570.45,3280.64 h60
  text "Round" at 6814.77,3280.64 h60
  text "Top Layer - Bottom Layer" at 7175.11,3280.64 h60
  text "39" at 5631.52,3181.02 h60
  text "12.00mil (0.305mm)" at 5948.7,3181.02 h60
  text "PTH" at 6570.45,3181.02 h60
  text "Round" at 6814.77,3181.02 h60
  text "Top Layer - Bottom Layer" at 7175.11,3181.02 h60
  text "9" at 5631.52,3081.4 h60
  text "16.00mil (0.406mm)" at 5948.7,3081.4 h60
  text "PTH" at 6570.45,3081.4 h60
  text "Round" at 6814.77,3081.4 h60
  text "Top Layer - Bottom Layer" at 7175.11,3081.4 h60
  text "22" at 5631.52,2981.77 h60
  text "40.00mil (1.016mm)" at 5948.7,2981.77 h60
  text "PTH" at 6570.45,2981.77 h60
  text "Round" at 6814.77,2981.77 h60
  text "Top Layer - Bottom Layer" at 7175.11,2981.77 h60
  text "3" at 5631.52,2882.15 h60
  text "47.24mil (1.200mm)" at 5948.7,2882.15 h60
  text "PTH" at 6570.45,2882.15 h60
  text "Round" at 6814.77,2882.15 h60
  text "Top Layer - Bottom Layer" at 7175.11,2882.15 h60
  text "3" at 5631.52,2782.53 h60
  text "63.00mil (1.600mm)" at 5948.7,2782.53 h60
  text "PTH" at 6570.45,2782.53 h60
  text "Round" at 6814.77,2782.53 h60
  text "Top Layer - Bottom Layer" at 7175.11,2782.53 h60
  text "4" at 5631.52,2682.91 h60
  text "70.87mil (1.800mm)" at 5948.7,2682.91 h60
  text "PTH" at 6570.45,2682.91 h60
  text "Round" at 6814.77,2682.91 h60
  text "Top Layer - Bottom Layer" at 7175.11,2682.91 h60
  text "105 Total" at 5631.52,2583.29 h60
  text ".Layer_Name" at 577,-858.49 h60
M17 Embedded Cavity:
  text ".Layer_Name" at 577,-858.49 h60
M18 Embedded Assembly:
  text ".Layer_Name" at 577,-858.49 h60
M19 Embedded Keepout:
  text ".Layer_Name" at 577,-858.49 h60

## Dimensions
3470,1037 to 1520,1037 on M2 Board Dimensions
1520,3037 to 1520,1037 on M2 Board Dimensions
0,-400 to 1000,-400 on M2 Board Dimensions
